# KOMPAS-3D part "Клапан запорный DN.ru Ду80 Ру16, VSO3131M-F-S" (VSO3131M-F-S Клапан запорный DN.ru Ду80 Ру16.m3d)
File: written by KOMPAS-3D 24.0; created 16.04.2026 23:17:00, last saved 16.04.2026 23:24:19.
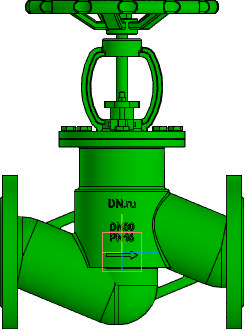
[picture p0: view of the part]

Document properties: Автор: R2D2; Полное имя файла: E:\Работа\Зайцев\VSO3131M-F-S Клапан запорный DN.ru Ду15-100 Ру16\DN80\VSO3131M-F-S Клапан запорный DN.ru Ду80 Ру16.m3d

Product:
- Part/product: Клапан запорный DN.ru Ду80 Ру16  | designation VSO3131M-F-S
    Масса: 20.25
    Раздел спецификации: Прочие изделия
    Примечание: D090-02953

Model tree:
1. Операция без истории:2

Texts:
  VSO3131M-F-S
